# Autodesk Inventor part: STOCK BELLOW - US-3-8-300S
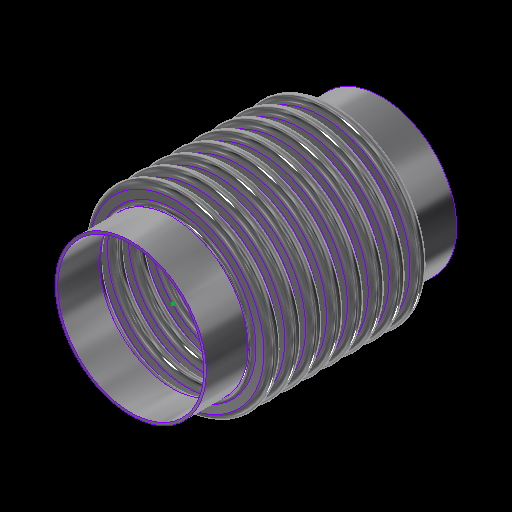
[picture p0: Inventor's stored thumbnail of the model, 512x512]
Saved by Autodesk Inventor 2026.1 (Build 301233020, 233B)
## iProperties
Category: 22 GA (0.030 THICK)
RuleStatus: InUse
Created: 2024-01
Part Number: STOCK BELLOW - US-3-8-300S
Project: =STOCK BELLOWS: <Stock Number><SFILL>
Material: ASTM A240-304
Description: =STOCK BELLOWS: <Stock Number>, <SID_> I.D., <SOD_> O.D., <SPLY_> PLY, <Category>, <SNET_CONS> CONS.<PITCH_><STANGENT_> TANGENT<SFILL>
Document SubType Name: Sheet Metal
Designer: GS
Stock Number: U.S-3-8-300S
Surface Area: 1826.32 cm^2
Volume: 137.186 cm^3
Sheet Metal Rule: Default
Appearance: STAINLESS STEEL
Mass: 1105.35 g
Density: 8.05729 g/cm^3
THK: 0.036
ID: 3.500
OD: 4.250
CONS_: 2
PITCH: 0.500
TANGENT: 0.500
BELLOWS_UPSET: 0.000
d79: 1.000
d82: 1.000
d83: 26.000
d84: 24.000
d174: 8
d214: 8
STHK_: 0.030
SID_: 3.500
SOD_: 4.500
SPITCH_: 0.500
STANGENT__: 1.000
SBELLOWS_UPSET_: 0.000
SDIFF_TAN: 1.000
d252: 2
d275: 2
d287: 0.050
d289: 0.500
d290: 0.000
SOD_NECK: 3 5/8
PLY: 1
PSET: 4.178
PBAR: 1.035
COUNTER: 1.500
NET_TUBE: 3.071
CONS: 2
S_CONS: 0
NET_CONS: 2
ID_M: 88.90 mm
OD_M: 107.95 mm
THK_M: 0.91 mm
ID_U: 3.500 in
OD_U: 4.250 in
THK_U: 0.036 in
TANGENT2: 0.500
TAN_TO_TAN: 1.000 in
d80: 2.571
d81: 10
SID: 2.375
SCONS_: 8
SPITCH: 0.250
STANGENT_: 1.000
SBELLOWS_UPSET: 0.000
SNET_CONS: 8
SS_CONS: 0
SCONS: 8
d190: 8
d191: 1
d192: 1
d193: 8
d194: 0
SIZE: 3.00
PRESSURE: 300
d230: 8
STANGENT: 4.000
SPLY_: 2
d233: 8
d234: 0
d263: 2
d265: 1
d268: 2
d269: 0
d286: 2
d288: 1
d291: 2
d292: 0
SREROLL: 0.750
BLETP: 0.000 ul
PRES_Copy: 85
MATTABLE: 20 GA (0.036 THICK)
PART_NUMBER: U.S-3-8-300S
PITCH_: =, <SPITCH_> PITCH,
CFILL: .
SFILL: .
MESH: ,
COMP: 0.57
EXT: 0.29
LAT: 0.19
ANG: 573
ASR: 4230
LSR: 6345
ANSR: 148
PRES: 300
COMPM: 5.7
EXTM: 2.85
LATM: 1.90
ASRM: 740.800
PRESM: 20.684
LSRM: 1111.200
ANSRM: 25.919
TEMPMIN: 20
TEMPMAX: 800
TEMPMINM: -7
TEMPMAXM: 427
WEIGHTM: 1.105
WEIGHT: 2.437
Author: GS
Keywords: 20 GA (0.036 THICK)
Comments: =STOCK BELLOW - <STOCK NUMBER>
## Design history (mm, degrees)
sketch "Sketch2"
  geometry: L1 (0, -177.245)-(0, 562.856) reference; L2 (45.364, 0)-(44.45, 0); L3 (48.082, -2.718)-(50.343, -2.718); L4 (48.082, -3.632)-(50.343, -3.632); L5 (50.343, -9.982)-(48.082, -9.982); L6 (50.343, -9.068)-(48.082, -9.068); L7 (45.364, -12.7)-(44.45, -12.7); L8 (48.082, 0)-(48.082, -12.7); L9 (50.343, -6.35)-(53.975, -6.35); L10 (44.45, 0)-(44.45, -12.7); L11 (20.376, 102.841)-(20.376, 101.926); L12 (58.262, 457.127)-(58.262, 349.177); L13 (58.262, 444.427)-(58.262, 336.477); L14 (93.133, -58.817)-(93.133, -71.517); L15 (118.746, -66.401)-(118.746, -66.401); L16 (50.343, -9.068)-(50.343, -9.982); L17 (48.082, -9.068)-(48.082, -9.982); L18 (48.082, -9.525)-(50.343, -9.525); L19 (53.975, 0)-(53.975, -12.7); L20 (-50.343, -9.068)-(-50.343, -9.982); L21 (-50.343, -2.718)-(-48.082, -2.718); L22 (-50.343, -3.632)-(-48.082, -3.632); L23 (-48.082, -9.068)-(-50.343, -9.068); L24 (-50.343, -9.525)-(-48.082, -9.525); L25 (-48.082, -9.982)-(-50.343, -9.982); L26 (-48.082, -9.068)-(-48.082, -9.982); L27 (-44.45, 0.653)-(-44.45, -12.047); L28 (-48.082, -6.35)-(-44.45, -6.35); L29 (-50.343, 0.653)-(-50.343, -12.7); L30 (-53.061, 0)-(-53.975, 0); L31 (-53.975, 0)-(-53.975, -12.7); L32 (-53.061, -12.7)-(-53.975, -12.7); A1 r 2.718 centre (48.082, 0) between (45.364, 0) and (48.082, -2.718); A2 r 3.632 centre (48.082, 0) between (44.45, 0) and (48.082, -3.632); A3 r 3.632 centre (50.343, -6.35) between (50.343, -9.982) and (50.343, -2.718); A4 r 2.718 centre (50.343, -6.35) between (50.343, -9.068) and (50.343, -3.632); A5 r 2.718 centre (48.082, -12.7) between (48.082, -9.982) and (45.364, -12.7); A6 r 3.632 centre (48.082, -12.7) between (48.082, -9.068) and (44.45, -12.7); A7 r 3.175 centre (50.343, -6.35) between (50.343, -9.525) and (53.518, -6.35); A8 r 3.175 centre (48.082, -12.7) between (48.082, -9.525) and (44.907, -12.7); A9 r 2.718 centre (-50.343, -12.7) between (-50.343, -9.982) and (-53.061, -12.7); A10 r 2.718 centre (-48.082, -6.35) between (-48.082, -9.068) and (-48.082, -3.632); A11 r 3.175 centre (-48.082, -6.35) between (-48.082, -9.525) and (-44.907, -6.35); A12 r 3.632 centre (-48.082, -6.35) between (-48.082, -9.982) and (-48.082, -2.718); A13 r 3.175 centre (-50.343, -12.7) between (-50.343, -9.525) and (-53.518, -12.7); A14 r 3.632 centre (-50.343, -12.7) between (-50.343, -9.068) and (-53.975, -12.7); A15 r 2.718 centre (-50.343, 0) between (-53.061, 0) and (-50.343, -2.718); A16 r 3.632 centre (-50.343, 0) between (-53.975, 0) and (-50.343, -3.632); 10 further points
  constraints: 62 end point, 38 point on circle, 20 tangent, 16 centre point, 12 parallel, 9 midpoint, 7 vertical, 6 coincident, 6 concentric, 6 point on line, 4 equal radius, 4 perpendicular, 3 horizontal, 1 collinear, 1 horizontal alignment, 10 other
  dimensions: "THK" = 0.9144 distance of L11.start L11.end; "ID" = 88.9 distance of L11.end point (20.376, 13.026); "OD" = 107.95 distance of L12.start L12.end; "PITCH" = 12.7 distance of L12.start L13.start; "TANGENT" = 12.7 distance of L14.start L14.end; "BELLOWS_UPSET" = 0 distance of L15.start L15.end; "d43" = 88.9 diameter of L10 L1 (= ID); "d44" = 107.95 diameter of L9.end L1 (= OD); "d45" = 0.9144 distance between parallel lines of L5 L6 (computed from THK, PLY); "d46" = 3.6322 radius of A3 (computed from PITCH, THK, PLY); "UPSET_PITCH" = 12.7 distance of L2.end L7.end (derived); "SIDEWALL_ANGLE" = 360 deg dimension on L3 L9 (derived); "CON_GAP" = 5.4356 distance of point (48.082, -9.068) point (48.082, -3.632) (derived); "TAN1" = 4.98728 dimension on A8 (derived); "TAN2" = 4.98728 dimension on A7 (derived); "LEG1" = 2.2606 distance of L18.start L18.end (derived); "d278" = 0.9144 distance between parallel lines of L25 L23 (derived); "d279" = 3.6322 radius of A12 (derived); "d280" = 12.7 distance of L30.end L31.end (derived); "d281" = 360 deg dimension on L21 L28 (derived); "d282" = 5.4356 distance of point (-50.343, -9.068) point (-50.343, -3.632) (derived); "d283" = 4.98728 dimension on A13 (derived); "d284" = 4.98728 dimension on A11 (derived); "d285" = 2.2606 distance of L24.start L24.end (derived); "d293" = 88.9 diameter of L27 L1 (derived); "d294" = 107.95 diameter of L31 L1 (derived)
  node "Sketch Rectangular Pattern1" dims "d31" = 25.4, "ID" = 88.9
  node "Sketch Rectangular Pattern2" dims "d39" = 25.4, "PITCH" = 12.7
revolve "CONS" stored, may be unused: angle "d48" = 90 deg
node "BELLOW MIDPLANE"
pattern_linear "Rectangular Pattern2" dims "d52" = 12.7 (= UPSET_PITCH)
sketch "Sketch5"
  geometry: C1 r 45.364 at (0, 0) reference; C2 r 44.45 at (0, 0) reference
extrude "TANGENT" new body sketch "Sketch5" distance "d53" = 12.7 (= TANGENT); taper "d54" = 0 deg
revolve "SAMETAN" stored, may be unused: angle "d65" = 90 deg
revolve "DIFFTAN" stored, may be unused: angle "d70" = 90 deg
sketch "Sketch9"
  geometry: L1 (53.319, 0)-(-53.319, 0) reference; L2 (0, -17.78)-(0, 17.78) reference; L3 (38.085, 0)-(-38.085, 0); L4 (38.085, -11.906)-(38.085, 11.906); L5 (25.385, -11.906)-(25.385, 11.906); L6 (13.15, 11.906)-(13.15, -11.906); L7 (-25.385, -11.906)-(-25.385, 11.906); L8 (-38.085, -11.906)-(-38.085, 11.906); L9 (37.291, -11.906)-(37.291, 11.906); L10 (38.085, -11.906)-(37.291, -11.906); L11 (38.085, 11.906)-(37.291, 11.906); L12 (13.546, 11.906)-(12.753, 11.906); L13 (12.753, 11.906)-(12.753, -11.906); L14 (12.753, -11.906)-(13.546, -11.906); L15 (13.546, -11.906)-(13.546, 11.906); L16 (-13.546, 11.906)-(-13.546, -11.906); L17 (-13.15, 11.906)-(-13.15, -11.906); L18 (-13.546, -11.906)-(-12.753, -11.906); L19 (-12.753, -11.906)-(-12.753, 11.906); L20 (-12.753, 11.906)-(-13.546, 11.906); L21 (-38.085, -11.906)-(-37.291, -11.906); L22 (-37.291, -11.906)-(-37.291, 11.906); L23 (-37.291, 11.906)-(-38.085, 11.906); L24 (-38.085, 11.906)-(-38.085, -11.906); L25 (38.085, -0.397)-(-38.085, -0.397); L26 (-38.085, -0.397)-(-38.085, 0.397); L27 (-38.085, 0.397)-(38.085, 0.397); L28 (38.085, 0.397)-(38.085, -0.397); L29 (-38.085, 11.906)-(38.085, 11.906); L30 (38.085, 11.906)-(38.085, 12.7); L31 (38.085, 12.7)-(-38.085, 12.7); L32 (-38.085, 12.7)-(-38.085, 11.906); L33 (38.085, -11.906)-(-38.085, -11.906); L34 (-38.085, -11.906)-(-38.085, -12.7); L35 (-38.085, -12.7)-(38.085, -12.7); L36 (38.085, -12.7)-(38.085, -11.906); 30 further points
  constraints: 68 end point, 13 midpoint, 13 parallel, 8 horizontal, 7 perpendicular, 6 equal length, 3 point on line, 2 vertical, 14 other
  dimensions: "d115" = 23.8125 distance of L4.start L4.end (derived); "d116" = 12.7 distance between parallel lines of L4 L5 (derived); "d117" = 12.23516 distance between parallel lines of L5 L6 (derived); "d125" = 38.53427 distance between parallel lines of L7 L6 (derived); "d127" = 12.7 distance between parallel lines of L8 L7 (derived); "d128" = 24.93516 distance between parallel lines of L6 L4 (derived); "d130" = 76.16943 distance between parallel lines of L8 L4 (derived); "RULER_THK" = 0.79375 distance between parallel lines of L4 L9; "d135" = 0.79375 distance of L13.end L14.end (derived); "d138" = 26.29911 distance of L13.end L16.end (derived); "d143" = 0.79375 distance of L22.end L8.end (derived); "d144" = 0.79375 distance between parallel lines of L27 L25 (derived)
extrude "RULER" join sketch "Sketch9" distance "d149" = 0.79375 (derived); taper "d150" = 0 deg
extrude "BARS" join sketch "Sketch9" distance "d151" = 0.79375 (derived); taper "d152" = 0 deg
pattern_linear "Rectangular Pattern4" dims "d155" = 26.29911 (derived)
sketch "Sketch13"
  geometry: L1 (93.149, -52.467)-(93.149, -77.867); L2 (45.974, 0)-(44.45, 0); L3 (45.974, -12.7)-(44.45, -12.7); L4 (53.213, -10.287)-(48.387, -10.287); L5 (53.213, -8.763)-(48.387, -8.763); L6 (53.213, -6.35)-(57.15, -6.35); L7 (48.387, -2.413)-(53.213, -2.413); L8 (48.387, 0)-(48.387, -12.7); L9 (44.45, 0)-(44.45, -12.7); L10 (58.254, -382.131)-(58.254, -496.431); L11 (58.254, -394.831)-(58.254, -509.131); L12 (58.254, -420.231)-(58.254, -534.531); L13 (58.254, -432.931)-(58.254, -547.231); L14 (58.254, -445.631)-(58.254, -559.931); L15 (58.254, -458.331)-(58.254, -572.631); L16 (58.254, -471.031)-(58.254, -585.331); L17 (58.254, -407.531)-(58.254, -521.831); L18 (20.376, 102.688)-(20.376, 101.926); L19 (48.387, -3.937)-(53.213, -3.937); L20 (0, -722.935)-(0, 240.292) reference; L21 (-23.752, 0)-(142.514, 0) reference; A1 r 2.413 centre (48.387, 0) between (45.974, 0) and (48.387, -2.413); A2 r 2.413 centre (48.387, -12.7) between (48.387, -10.287) and (45.974, -12.7); A3 r 3.937 centre (48.387, -12.7) between (48.387, -8.763) and (44.45, -12.7); A4 r 2.413 centre (53.213, -6.35) between (53.213, -8.763) and (53.213, -3.937); A5 r 3.937 centre (53.213, -6.35) between (53.213, -10.287) and (53.213, -2.413); A6 r 3.937 centre (48.387, 0) between (44.45, 0) and (48.387, -3.937); 6 further points; 1 other entity
  constraints: 38 end point, 15 point on circle, 9 tangent, 6 centre point, 6 parallel, 5 vertical alignment, 4 point on line, 4 vertical, 3 coincident, 3 concentric, 2 collinear, 2 equal radius, 1 horizontal, 1 perpendicular, 23 other
  dimensions: "SBELLOWS_UPSET_" = 0 distance of point (118.762, -66.401) point (118.762, -66.401); "STOTAL_THK_BELLOW__" = 1.524 distance between parallel lines of L4 L5 (derived); "d224" = 3.937 radius of A5 (derived); "d225" = 12.7 distance of L2.end L3.end (derived); "SSIDEWALL_ANGLE_" = 0 deg angle of L7 L6 (derived); "SSCON_GAP_" = 4.826 distance of point (48.387, -8.763) point (48.387, -3.937) (derived); "d235" = 88.9 diameter of L9 L20 (derived); "d236" = 114.3 diameter of L6.end L20 (derived)
  node "Sketch Rectangular Pattern4" dims "d228" = 25.4
  node "Sketch Rectangular Pattern5" dims "d229" = 25.4
revolve "SBELLOW" stored, may be unused: angle "d197" = 90 deg
pattern_linear "Rectangular Pattern5" dims "d204" = 12.7 (derived)
revolve "STANGENT" stored, may be unused: angle "d240" = 90 deg
revolve "SSAMETAN" stored, may be unused: angle "d241" = 90 deg
revolve "SDIFFTAN" stored, may be unused: angle "d246" = 90 deg
revolve "INVCON" stored, may be unused: angle "d295" = 90 deg
pattern_linear "Rectangular Pattern6" dims "d298" = 12.7 (derived)
revolve "INVTANGENT" stored, may be unused: angle "d302" = 90 deg
revolve "INVSAMETAN" stored, may be unused: angle "d307" = 90 deg
revolve "INVDIFFTAN" stored, may be unused: angle "d312" = 90 deg
sketch "ID BELLOW MOUNT CALC"
  geometry: L1 (44.45, 0)-(38.1, 0); L2 (38.1, 0)-(38.1, 12.7); L3 (38.1, 12.7)-(44.45, 12.7); L4 (44.45, 12.7)-(44.45, 0); L5 (36.513, 12.7)-(35.598, 12.7); L6 (35.598, 12.7)-(35.598, 0); L7 (35.598, 0)-(36.513, 0); L8 (36.513, 0)-(36.513, 12.7); L9 (0, -2.54)-(0, 15.24) reference; L10 (-8.89, 0)-(53.34, 0) reference; 1 further point
  constraints: 16 end point, 5 parallel, 2 collinear, 2 horizontal, 2 perpendicular
  dimensions: "d314" = 12.7 distance of L5.end L6.end (derived); "d315" = 0.9144 distance of L5.start L5.end (derived); "IG" = 1.5875 distance between parallel lines of L2 L8; "PIPE_OD" = 88.9 diameter of L4 L9; "PIPE_WALL" = 6.35 distance of L2.end L3.end; "ID_MT_BELLOW" = 71.1962 diameter of L6 L9 (derived)
revolve "CFILL" stored, may be unused: angle "d320" = 90 deg
pattern_linear "Rectangular Pattern7" dims "d323" = 12.7 (derived)
revolve "SFILL" stored, may be unused: angle "d324" = 90 deg
pattern_linear "Rectangular Pattern8" dims "d327" = 12.7 (derived)
node "STOCK BELLOW MIDPLANE"
node "BELLOW"
sketch "Sketch6"
  geometry: L1 (-12.7, 45.364)-(0, 45.364); L2 (0, 45.364)-(0, 44.45); L3 (0, 44.45)-(-12.7, 44.45); L4 (-12.7, 44.45)-(-12.7, 45.364); L5 (10.16, 0)-(-60.96, 0) reference; L6 (-38.1, -89.422)-(-38.1, 153.44) reference; 1 further point
  constraints: 8 end point, 2 parallel, 1 horizontal, 1 perpendicular
  dimensions: "d61" = 12.7 distance of L2.end L3.end (derived); "d62" = 0.9144 distance of L1.end L2.end (derived); "d63" = 88.9 diameter of L3 L5 (derived); "d64" = 25.4 distance between parallel lines of L4 L6 (derived)
sketch "Sketch12"
  geometry: 1 further point
sketch "Sketch14"
  geometry: L1 (-25.4, 45.974)-(0, 45.974); L2 (0, 45.974)-(0, 44.45); L3 (0, 44.45)-(-25.4, 44.45); L4 (-25.4, 44.45)-(-25.4, 45.974); L5 (5.08, 0)-(-30.48, 0) reference; L6 (0, -9.195)-(0, 55.169) reference; 1 further point
  constraints: 8 end point, 2 parallel, 1 collinear, 1 horizontal, 1 perpendicular
  dimensions: "d237" = 1.524 distance of L3.end L1.start (derived); "d238" = 88.9 diameter of L3 L5 (derived); "d239" = 25.4 distance of L1.start L1.end (derived); "SOD_NECK" = 91.948 diameter of L1 L5 (derived)
sketch "Sketch15"
  geometry: L1 (-9.195, 0)-(55.169, 0) reference; L2 (44.45, -101.6)-(45.974, -101.6); L3 (45.974, -101.6)-(45.974, -127); L4 (45.974, -127)-(44.45, -127); L5 (44.45, -127)-(44.45, -101.6); L6 (0, -154.94)-(0, 40.64) reference; 1 further point
  constraints: 8 end point, 2 parallel, 1 horizontal, 1 perpendicular
  dimensions: "d205" = 25.4 distance of L4.end L2.start (derived); "d206" = 1.524 distance of L3.end L4.end (derived); "d207" = 88.9 diameter of L5 L6 (derived); "d208" = 101.6 distance between parallel lines of L1 L2 (derived)
node "TANGENT_"
node "SAME_TAN"
sketch "Sketch8"
  geometry: L1 (45.364, -25.4)-(44.45, -25.4); L2 (44.45, -25.4)-(44.45, -38.1); L3 (44.45, -38.1)-(45.364, -38.1); L4 (45.364, -38.1)-(45.364, -25.4); L5 (0, -48.26)-(0, 22.86) reference; L6 (-89.422, 0)-(153.44, 0) reference; 1 further point
  constraints: 8 end point, 2 parallel, 1 horizontal, 1 perpendicular
  dimensions: "d66" = 88.9 diameter of L2 L5 (derived); "TOTAL_THK_BELLOW" = 0.9144 distance of L2.end L3.end (derived); "d68" = 25.4 distance between parallel lines of L1 L6 (derived); "d69" = 12.7 distance of L1.end L2.end (derived)
node "DIFF_TAN"
node "Sketch Rectangular Pattern3" dims "d138" = 26.29911 (derived), "d141" = 25.4
node "SBELLOW_"
node "STANGENT_"
node "SSAME_TAN"
sketch "Sketch16"
  geometry: L1 (45.974, -101.6)-(44.45, -101.6); L2 (44.45, -101.6)-(44.45, -127); L3 (44.45, -127)-(45.974, -127); L4 (45.974, -127)-(45.974, -101.6); L5 (0, -154.94)-(0, 40.64) reference; L6 (-9.195, 0)-(55.169, 0) reference; 1 further point
  constraints: 8 end point, 2 parallel, 1 horizontal, 1 perpendicular
  dimensions: "SDIFF_TAN" = 25.4 distance of L3.end L1.start; "d243" = 1.524 distance of L2.end L3.end (derived); "d244" = 101.6 distance between parallel lines of L1 L6 (derived); "d245" = 88.9 diameter of L2 L5 (derived)
node "SDIFF_TAN"
body "Solid15"
sketch "Sketch17"
  geometry: L1 (53.975, 12.7)-(53.061, 12.7); L2 (53.061, 12.7)-(53.061, 0); L3 (53.061, 0)-(53.975, 0); L4 (53.975, 0)-(53.975, 12.7); L5 (0, -2.54)-(0, 15.24) reference; L6 (-10.795, 0)-(64.77, 0) reference; 2 further points
  constraints: 8 end point, 2 parallel, 1 horizontal, 1 midpoint, 1 perpendicular, 1 point on line
  dimensions: "INVTANGENT" = 12.7 distance of L3.end L1.start (derived); "d300" = 0.9144 distance of L1.start L1.end (derived); "d301" = 107.95 diameter of L4 L5 (derived)
body "Solid16"
sketch "Sketch18"
  geometry: L1 (53.975, -25.4)-(53.061, -25.4); L2 (53.061, -25.4)-(53.061, -38.1); L3 (53.061, -38.1)-(53.975, -38.1); L4 (53.975, -38.1)-(53.975, -25.4); L5 (-10.795, 0)-(64.77, 0) reference; L6 (0, -48.26)-(0, 22.86) reference; 1 further point
  constraints: 8 end point, 2 parallel, 1 horizontal, 1 perpendicular
  dimensions: "d303" = 25.4 distance between parallel lines of L1 L5 (derived); "d304" = 12.7 distance of L3.end L1.start (derived); "d305" = 0.9144 distance of L2.end L3.end (derived); "d306" = 107.95 diameter of L4 L6 (derived)
body "Solid17"
sketch "Sketch19"
  geometry: L1 (53.975, -25.4)-(53.061, -25.4); L2 (53.061, -25.4)-(53.061, -38.1); L3 (53.061, -38.1)-(53.975, -38.1); L4 (53.975, -38.1)-(53.975, -25.4); L5 (0, -48.26)-(0, 22.86) reference; L6 (-10.795, 0)-(64.77, 0) reference; 1 further point
  constraints: 8 end point, 2 parallel, 1 horizontal, 1 perpendicular
  dimensions: "d308" = 12.7 distance of L1.end L2.end (derived); "d309" = 107.95 diameter of L4 L5 (derived); "d310" = 0.9144 distance of L2.end L3.end (derived); "d311" = 25.4 distance between parallel lines of L1 L6 (derived)
body "Solid18"
body "Solid19"
body "Solid20"
other parameters: "BMPL" = -50.8, "PSET" = 106.1212 (computed from OD, THK, PLY) [user parameter], "PBAR" = 26.29911 (= 0.570796 x PITCH + OD - ID) [user parameter; used in 1 equation term], "COUNTER" = 15 [user parameter], "NET_TUBE" = 77.99823 (computed from CONS_, PBAR, TANGENT) [user parameter], "S_CONS" = 0 [user parameter; used in 1 equation term], "ID_M" = 88.9 (= ID) [user parameter], "OD_M" = 107.95 (= OD) [user parameter], "THK_M" = 0.9144 (= THK) [user parameter], "ID_U" = 88.9 (= ID) [user parameter], "OD_U" = 107.95 (= OD) [user parameter], "THK_U" = 0.9144 (= THK) [user parameter], "D_UNITS" = 0 [user parameter], "TANGENT2" = 12.7 [user parameter], "TAN_TO_TAN" = 25.4 [user parameter], "OD_NECK" = 90.7288 [user parameter], "d79" = 25.4, "d80" = 65.29823 [user parameter], "d82" = 25.4, "d83" = 660.4, "d84" = 609.6, "sa_0" = 4, "FRAME_THK" = 0.79375 [user parameter], "CON_FLAT" = 12.23516 [user parameter], "SID" = 60.325 [user parameter], "SPITCH" = 6.35 [user parameter], "STANGENT_" = 25.4 [user parameter], "SBELLOWS_UPSET" = 0 [user parameter], "SS_CONS" = 0 [user parameter], "STAN_TO_TAN_" = 101.6 [user parameter], "d100" = 1.524 [user parameter], "d191" = 25.4 [user parameter], "d194" = 0 [user parameter], "STANGENT" = 101.6 [user parameter], "d234" = 0 [user parameter], "SUPSET_PITCH_" = 12.7 [user parameter], "d269" = 0 [user parameter], "d287" = 1.27, "d289" = 12.7, "d290" = 0, "d292" = 0 [user parameter], "Thickness" = 3.048 (derived), "KFactor" = 4.4, "BendRadius" = 3.048 (derived), "BendReliefWidth" = 3.048 (derived), "BendReliefDepth" = 1.524 (derived), "CornerReliefSize" = 12.192 (derived), "SeamGap" = 0.00508, "MinimumRemnant" = 6.096 (derived), "TransitionRadius" = 3.048 (derived), "JacobiRadiusSize" = 3.048 (derived), "GapSize" = 3.048 (derived), "SREROLL" = 19.05 [user parameter], "CUR_STK_PITCH" = 12.7 [user parameter], "d328" = -50.8 (derived), "ASR" = 42300 [user parameter], "LSR" = 63450 [user parameter], "BLETP" = 0 [user parameter], "ASRM" = 7407.999 [user parameter], "PRESM" = 206.83949 [user parameter], "LSRM" = 11111.9985 [user parameter], "ANSRM" = 259.1924 [user parameter], "TEMPMIN" = 2664.83333 [user parameter], "TEMPMAX" = 6998.16667 [user parameter], "TEMPMINM" = 2664.83333 [user parameter], "TEMPMAXM" = 6998.16667 [user parameter], "WEIGHT" = 11.05347 [user parameter], "WEIGHTM" = 0.01105 [user parameter]
